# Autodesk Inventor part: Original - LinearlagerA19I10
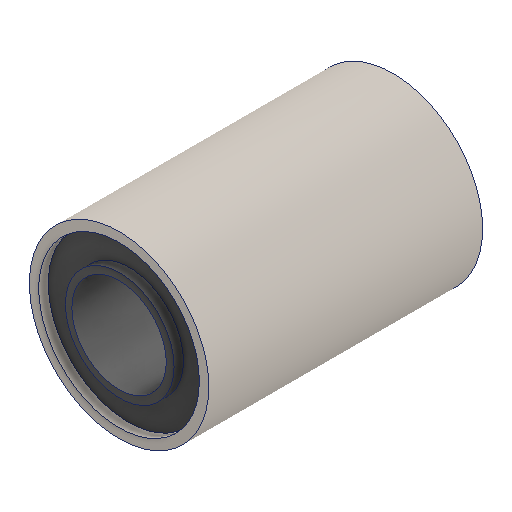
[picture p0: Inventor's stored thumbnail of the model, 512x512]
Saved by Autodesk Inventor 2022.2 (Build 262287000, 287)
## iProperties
Created: 2024-09
Part Number: Original - LinearlagerA19I10
Material: Generico
Document SubType Name: Modeling
Designer: 18907419
Density: 1 g/cm^3
Appearance: Default
Author: 18907419
Revision Number: ANY
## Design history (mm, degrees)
feature "Schnitt-Linear austragen3"
node "Solido1"
